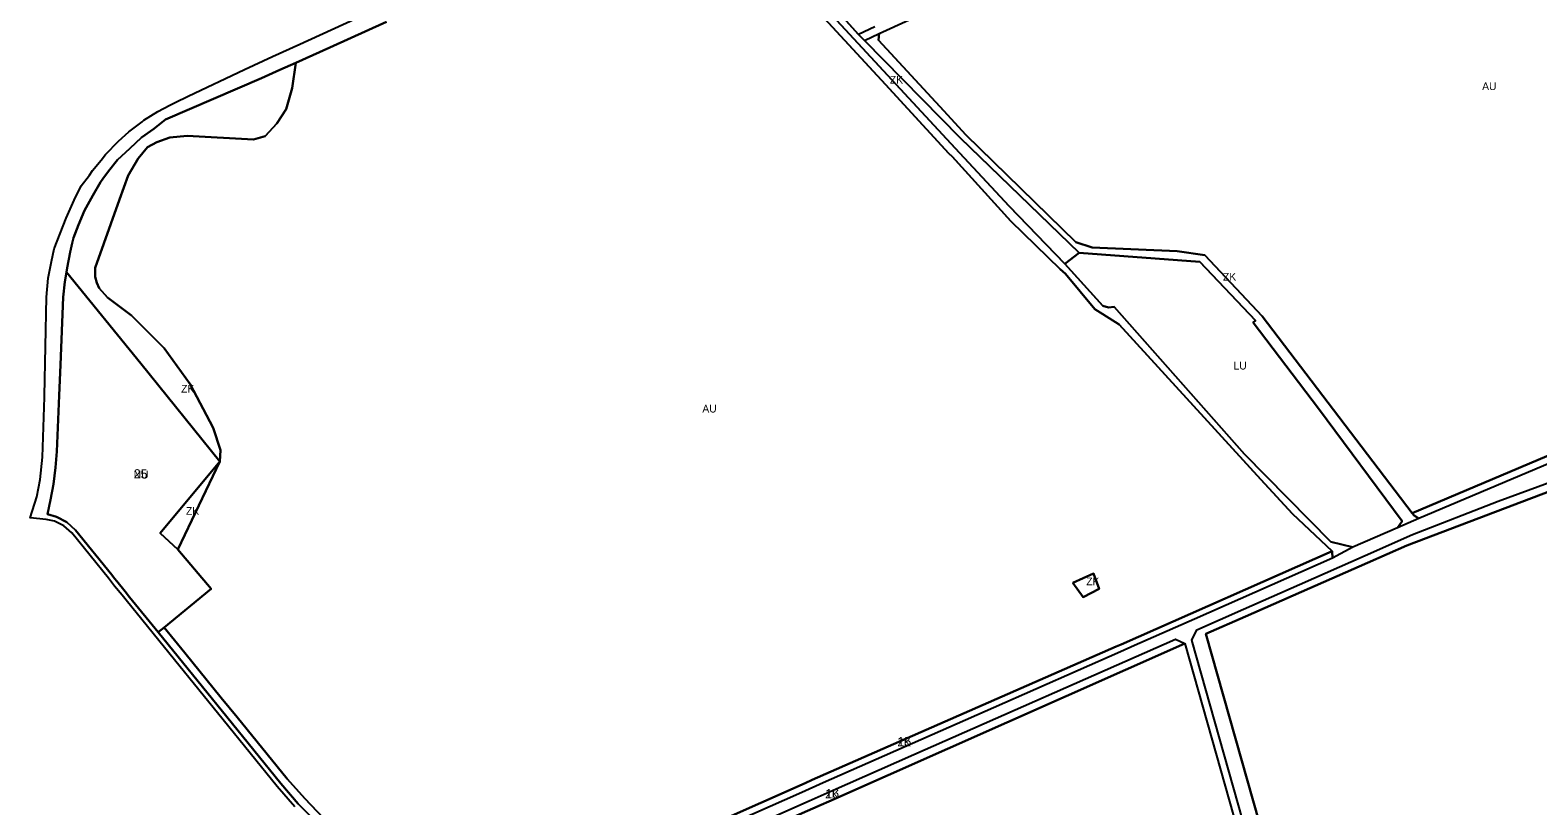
# Model space of a CAD drawing. Extents: x -522079 to -518833, y -1142398 to -1139961.
# Drawn here: x -521980 to -521001, y -1141186 to -1140682 of the extents above; entities that cross this region are included whole.
import ezdxf

# ---------------------------------------------------------------- set-up
doc = ezdxf.new("R2010")
doc.units = 0
for name, color, linetype in [('90640013', 7, 'Continuous'), ('90710013', 7, 'Continuous'), ('90710023', 7, 'Continuous'), ('90730023', 7, 'Continuous'), ('90750013', 7, 'Continuous'), ('90770013', 7, 'Continuous'), ('ID_navrh', 7, 'Continuous')]:
    doc.layers.add(name, color=color, linetype=linetype)

msp = doc.modelspace()

# ---------------------------------------------------------------- linework, layer by layer
at = {"layer": '90640013'}
for points in [[(-521501.14, -1140618.78), (-521441.99, -1140684.63), (-521438.02, -1140688.47), (-521375.87, -1140751.79), (-521298.55, -1140826.47), (-521307.86, -1140833.61), (-521344.11, -1140796.22), (-521379.23, -1140758.51), (-521505.44, -1140622.18)], [(-521808.03, -1141186.29), (-521819.49, -1141173.11), (-521854.62, -1141129.62), (-521886.17, -1141090.77), (-521917.71, -1141051.91), (-521920.31, -1141048.71), (-521925.3, -1141042.86), (-521929.14, -1141037.67), (-521952.92, -1141008.37), (-521958.05, -1141003.66), (-521964.16, -1141000.63), (-521969.71, -1140999.55), (-521980.02, -1140998.54), (-521975.77, -1140984.83), (-521973.56, -1140973.69), (-521972.01, -1140959.19), (-521970.73, -1140920.13), (-521970.78, -1140919.37), (-521969.35, -1140855.23), (-521968.4, -1140842.82), (-521966.23, -1140832.06), (-521964.35, -1140823.92), (-521960.5, -1140813.97), (-521956.64, -1140803.89), (-521951.34, -1140792.2), (-521946.81, -1140782.96), (-521941.53, -1140776.07), (-521939.58, -1140773.02), (-521933.99, -1140766.2), (-521930.99, -1140762.54), (-521922.69, -1140753.87), (-521915.99, -1140747.92), (-521907.36, -1140741.3), (-521906.16, -1140740.38), (-521897.11, -1140734.61), (-521889.34, -1140730.49), (-521885.86, -1140728.85), (-521877.29, -1140724.81), (-521840.82, -1140707.39), (-521822.52, -1140699.01), (-521804.78, -1140690.88), (-521769.34, -1140674.65)], [(-521748.53, -1140676.5), (-521785.36, -1140693.05), (-521807.36, -1140702.96), (-521817.76, -1140707.64), (-521829.78, -1140713), (-521892.09, -1140739.95), (-521899.73, -1140746), (-521907.65, -1140751.59), (-521915.35, -1140758.73), (-521923.36, -1140766.09), (-521929.14, -1140773.45), (-521932.78, -1140778.46), (-521934.35, -1140780.63), (-521939.28, -1140789.17), (-521944.68, -1140798.86), (-521948.6, -1140808.27), (-521951.85, -1140816.81), (-521952.78, -1140820.25), (-521953.99, -1140825.94), (-521956.06, -1140836.18), (-521956.51, -1140838.94), (-521957.55, -1140845.37), (-521958.48, -1140855.25), (-521960.41, -1140899.15), (-521961.27, -1140919.13), (-521962.64, -1140955.52), (-521963.61, -1140965.78), (-521964.79, -1140976.78), (-521966.75, -1140986.81), (-521968.74, -1140996.16), (-521962.85, -1140997.93), (-521956.25, -1141001.25), (-521950.59, -1141006.47), (-521927.04, -1141035.61), (-521925.13, -1141037.95), (-521923.77, -1141039.61), (-521918.24, -1141046.46), (-521915.45, -1141049.99), (-521896.82, -1141072.9), (-521883.81, -1141088.91), (-521852.32, -1141127.72), (-521817.11, -1141171.17), (-521805.87, -1141184.18), (-521793.6, -1141196.53)]]:
    msp.add_lwpolyline(points, dxfattribs=at)
at = {"layer": '90710013'}
for points in [[(-521505.44, -1140622.18), (-521379.23, -1140758.51), (-521344.11, -1140796.22), (-521307.86, -1140833.61), (-521283.37, -1140860.94), (-521279.53, -1140861.89), (-521275.9, -1140861.47), (-521191.17, -1140957.11), (-521135.25, -1141014.2), (-521120.79, -1141017.67), (-521134.18, -1141024.63), (-521134.23, -1141020.21), (-521160.03, -1140995.91), (-521180.73, -1140973.62), (-521272.67, -1140872.95), (-521283.24, -1140866.3), (-521288.46, -1140863.02), (-521307.59, -1140840.17), (-521311.05, -1140836.96), (-521343.03, -1140805.79), (-521381.12, -1140763.92), (-521383.31, -1140761.88), (-521424.45, -1140717.21), (-521509.24, -1140625.15)], [(-521431.42, -1140679.77), (-521441.99, -1140684.63), (-521501.14, -1140618.78)], [(-521793.6, -1141196.53), (-521805.87, -1141184.18), (-521817.11, -1141171.17), (-521852.32, -1141127.72), (-521883.81, -1141088.91), (-521896.82, -1141072.9), (-521893.06, -1141069.8), (-521879.49, -1141086.24), (-521855.85, -1141115.33), (-521845.59, -1141127.96), (-521813.1, -1141167.95), (-521801.69, -1141180.84), (-521789.46, -1141193.57)]]:
    msp.add_lwpolyline(points, dxfattribs=at)
for points in [[(-521082.3, -1140995.42), (-521081.12, -1140996.97), (-521077.97, -1140999.02), (-521091.97, -1141005.03), (-521088.9, -1141000.66), (-521143.12, -1140927.46), (-521185.72, -1140871.68), (-521184.18, -1140870.5), (-521220.23, -1140832.37), (-521298.55, -1140826.47), (-521375.87, -1140751.79), (-521438.02, -1140688.47), (-521428.47, -1140683.93), (-521428.9, -1140688.4), (-521386.59, -1140734.32), (-521372.2, -1140749.84), (-521300.72, -1140819.47), (-521290.3, -1140823.03), (-521234.98, -1140825.42), (-521217.11, -1140828.01), (-521179.82, -1140867.68), (-521133.42, -1140928.49)], [(-521956.51, -1140838.94), (-521956.06, -1140836.18), (-521953.99, -1140825.94), (-521952.78, -1140820.25), (-521951.85, -1140816.81), (-521948.6, -1140808.27), (-521944.68, -1140798.86), (-521939.28, -1140789.17), (-521934.35, -1140780.63), (-521932.78, -1140778.46), (-521929.14, -1140773.45), (-521923.36, -1140766.09), (-521915.35, -1140758.73), (-521907.65, -1140751.59), (-521899.73, -1140746), (-521892.09, -1140739.95), (-521829.78, -1140713), (-521817.76, -1140707.64), (-521807.36, -1140702.96), (-521809.93, -1140719.56), (-521813.81, -1140733.11), (-521819.79, -1140742.52), (-521827.42, -1140750.62), (-521834.89, -1140752.79), (-521878.09, -1140750.44), (-521889.21, -1140751.5), (-521897.69, -1140754.5), (-521903.79, -1140757.88), (-521909.81, -1140765.14), (-521916.45, -1140776.17), (-521922.02, -1140791.92), (-521937.7, -1140836.22), (-521937.7, -1140842.11), (-521936.78, -1140845.99), (-521935.25, -1140849.47), (-521929.85, -1140855.48), (-521914.17, -1140867.15), (-521903.5, -1140877.67), (-521892.98, -1140888.32), (-521876.05, -1140911.7), (-521861.19, -1140940.1), (-521856.34, -1140954.66), (-521856.78, -1140962.03), (-521908.14, -1140898.33)], [(-521884.07, -1141019.15), (-521895.5, -1141008.4), (-521856.78, -1140962.03)], [(-521302.83, -1141040.76), (-521289.36, -1141034.73), (-521285.67, -1141044.64), (-521296.08, -1141050.04)]]:
    msp.add_lwpolyline(points, close=True, dxfattribs=at)
at = {"layer": '90710023'}
for points in [[(-521082.3, -1140995.42), (-520989.26, -1140956.04), (-520894.6, -1140917.89), (-520890.08, -1140915.49), (-520882.47, -1140917.37), (-520896.33, -1140923.45), (-520987.34, -1140960.66), (-521077.97, -1140999.02), (-521081.12, -1140996.97)], [(-521134.23, -1141020.21), (-521134.18, -1141024.63), (-521223.67, -1141064.26), (-521262.72, -1141081.47), (-521271.86, -1141085.49), (-521354.37, -1141121.84), (-521464.85, -1141170.68), (-521478.81, -1141176.87), (-521531.28, -1141200.09), (-521696.71, -1141273.51), (-521705, -1141272.16), (-521476.67, -1141170.91), (-521472.07, -1141168.66), (-521274.53, -1141082.16), (-521271.3, -1141080.74)], [(-521692.02, -1141284.07), (-521691.15, -1141278.7), (-521609.81, -1141242.59), (-521474.13, -1141182.35), (-521460.33, -1141176.23), (-521405.94, -1141152.24), (-521236.08, -1141077.32), (-521230.09, -1141080.11), (-521461.21, -1141182.74), (-521466.3, -1141184.96)]]:
    msp.add_lwpolyline(points, close=True, dxfattribs=at)
msp.add_lwpolyline([(-521177.35, -1141247.92), (-521225.53, -1141078.04), (-521222.3, -1141071.25), (-521191.96, -1141057.88), (-521155.63, -1141041.85), (-521112.83, -1141022.98), (-521082.18, -1141009.47), (-521026.59, -1140987.63), (-520970.5, -1140967.09), (-520956.56, -1140961.79), (-520893.74, -1140937.98), (-520892.3, -1140942.89), (-520959.78, -1140968.46), (-520964.29, -1140970.32), (-521085.77, -1141016.42), (-521111.47, -1141027.75), (-521154.28, -1141046.62), (-521190.59, -1141062.63), (-521216.29, -1141073.97), (-521143.42, -1141331.19)], dxfattribs=at)
at = {"layer": '90730023'}
msp.add_lwpolyline([(-521893.06, -1141069.8), (-521896.82, -1141072.9), (-521915.45, -1141049.99), (-521918.24, -1141046.46), (-521923.77, -1141039.61), (-521925.13, -1141037.95), (-521927.04, -1141035.61), (-521950.59, -1141006.47), (-521956.25, -1141001.25), (-521962.85, -1140997.93), (-521968.74, -1140996.16), (-521966.75, -1140986.81), (-521964.79, -1140976.78), (-521963.61, -1140965.78), (-521962.64, -1140955.52), (-521961.27, -1140919.13), (-521960.41, -1140899.15), (-521958.48, -1140855.25), (-521957.55, -1140845.37), (-521956.51, -1140838.94), (-521908.14, -1140898.33), (-521856.78, -1140962.03), (-521895.5, -1141008.4), (-521884.07, -1141019.15), (-521862.5, -1141044.56)], close=True, dxfattribs=at)
at = {"layer": '90750013'}
for points in [[(-520989.26, -1140956.04), (-521082.3, -1140995.42), (-521133.42, -1140928.49), (-521179.82, -1140867.68), (-521217.11, -1140828.01), (-521234.98, -1140825.42), (-521290.3, -1140823.03), (-521300.72, -1140819.47), (-521372.2, -1140749.84), (-521386.59, -1140734.32), (-521428.9, -1140688.4), (-521428.47, -1140683.93), (-521306.81, -1140628.37), (-521187.8, -1140573.75), (-521174.07, -1140567.72), (-521038.29, -1140505.39), (-520909.31, -1140446.06)], [(-521509.24, -1140625.15), (-521424.45, -1140717.21), (-521383.31, -1140761.88), (-521381.12, -1140763.92), (-521343.03, -1140805.79), (-521311.05, -1140836.96), (-521307.59, -1140840.17), (-521288.46, -1140863.02), (-521283.24, -1140866.3), (-521272.67, -1140872.95), (-521180.73, -1140973.62), (-521160.03, -1140995.91), (-521134.23, -1141020.21), (-521271.3, -1141080.74), (-521274.53, -1141082.16), (-521472.07, -1141168.66), (-521476.67, -1141170.91), (-521705, -1141272.16)], [(-521789.46, -1141193.57), (-521801.69, -1141180.84), (-521813.1, -1141167.95), (-521845.59, -1141127.96), (-521855.85, -1141115.33), (-521879.49, -1141086.24), (-521893.06, -1141069.8), (-521862.5, -1141044.56), (-521884.07, -1141019.15), (-521856.78, -1140962.03), (-521856.34, -1140954.66), (-521861.19, -1140940.1), (-521876.05, -1140911.7), (-521892.98, -1140888.32), (-521903.5, -1140877.67), (-521914.17, -1140867.15), (-521929.85, -1140855.48), (-521935.25, -1140849.47), (-521936.78, -1140845.99), (-521937.7, -1140842.11), (-521937.7, -1140836.22), (-521922.02, -1140791.92), (-521916.45, -1140776.17), (-521909.81, -1140765.14), (-521903.79, -1140757.88), (-521897.69, -1140754.5), (-521889.21, -1140751.5), (-521878.09, -1140750.44), (-521834.89, -1140752.79), (-521827.42, -1140750.62), (-521819.79, -1140742.52), (-521813.81, -1140733.11), (-521809.93, -1140719.56), (-521807.36, -1140702.96), (-521785.36, -1140693.05), (-521748.53, -1140676.5)], [(-521692.02, -1141284.07), (-521466.3, -1141184.96), (-521461.21, -1141182.74), (-521230.09, -1141080.11), (-521201.01, -1141182.77), (-521192.96, -1141211.21)]]:
    msp.add_lwpolyline(points, dxfattribs=at)
for points in [[(-520727.16, -1141148.38), (-520890.16, -1141218.54), (-520895.96, -1141221.04), (-521038.45, -1141284.46), (-521081.35, -1141303.56), (-521117.38, -1141319.6), (-521143.42, -1141331.19), (-521216.29, -1141073.97), (-521190.59, -1141062.63), (-521154.28, -1141046.62), (-521111.47, -1141027.75), (-521085.77, -1141016.42), (-520964.29, -1140970.32), (-520959.78, -1140968.46), (-520892.3, -1140942.89), (-520888.93, -1140954.41), (-520885.58, -1140965.84), (-520881.52, -1140979.72), (-520872.93, -1141009.05), (-520861.45, -1141049.84), (-520847.24, -1141100.33), (-520846.14, -1141104.23), (-520733.88, -1141082.24)], [(-521302.83, -1141040.76), (-521296.08, -1141050.04), (-521285.67, -1141044.64), (-521289.36, -1141034.73)]]:
    msp.add_lwpolyline(points, close=True, dxfattribs=at)
at = {"layer": '90770013'}
msp.add_lwpolyline([(-521120.79, -1141017.67), (-521135.25, -1141014.2), (-521191.17, -1140957.11), (-521275.9, -1140861.47), (-521279.53, -1140861.89), (-521283.37, -1140860.94), (-521307.86, -1140833.61), (-521298.55, -1140826.47), (-521220.23, -1140832.37), (-521184.18, -1140870.5), (-521185.72, -1140871.68), (-521143.12, -1140927.46), (-521088.9, -1141000.66), (-521091.97, -1141005.03)], close=True, dxfattribs=at)

# ---------------------------------------------------------------- texts
at = {"layer": '90710013'}
for rotation, p in [(0, (-521421.59, -1140716.534)), (0, (-521205.204, -1140844.48)), (360, (-521881.935, -1140917.202)), (0, (-521878.783, -1140996.527)), (0, (-521294.079, -1141042.385))]:
    msp.add_text('ZK', height=5, rotation=rotation, dxfattribs=at).set_placement(p)
at = {"layer": '90710023'}
for p in [(-521416.626, -1141146.86), (-521463.501, -1141180.695)]:
    msp.add_text('ZK', height=5, rotation=0, dxfattribs=at).set_placement(p)
at = {"layer": '90730023'}
msp.add_text('NU', height=5, rotation=360, dxfattribs=at).set_placement((-521912.76, -1140972.978))
at = {"layer": '90750013'}
for rotation, p in [(0, (-521036.884, -1140720.74)), (360, (-521543.406, -1140930.16))]:
    msp.add_text('AU', height=5, rotation=rotation, dxfattribs=at).set_placement(p)
at = {"layer": '90770013'}
msp.add_text('LU', height=5, rotation=0, dxfattribs=at).set_placement((-521198.38, -1140902.226))
at = {"layer": 'ID_navrh'}
for s, rotation, p in [('25', 0, (-521912.76, -1140972.978)), ('15', 360, (-521416.626, -1141146.86))]:
    msp.add_text(s, height=6, rotation=rotation, dxfattribs=at).set_placement(p)
msp.add_text('16', height=6, dxfattribs=at).set_placement((-521463.501, -1141180.695))

doc.saveas('drawing.dxf')
